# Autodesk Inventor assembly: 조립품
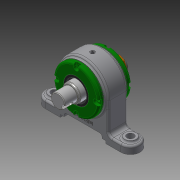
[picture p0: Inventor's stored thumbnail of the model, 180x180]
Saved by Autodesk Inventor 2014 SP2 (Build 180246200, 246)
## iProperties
Created: 2019-05
Part Number: 조립품
Document SubType Name: Assembly
Designer: gs
Author: gs
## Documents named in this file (9)
- C:\Users\gs\Desktop\490504V1029\조립품.iam
- C:\Users\gs\Desktop\490504V1029\본체.ipt
- C:\Users\gs\Desktop\490504V1029\축.ipt
- C:\Users\gs\Desktop\490504V1029\앵귤러 볼 베어링 7205.ipt
- C:\Users\gs\Desktop\490504V1029\커버.ipt
- C:\Users\gs\Desktop\490504V1029\칼라.ipt
- C:\Users\gs\Desktop\490504V1029\오일 실 28 40 5 B.ipt
- C:\Users\gs\Desktop\490504V1029\베어링너트.ipt
- C:\Users\gs\Desktop\490504V1029\개스킷.ipt
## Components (2 placed, 1 different names)
1. 개스킷:1
2. 개스킷:3
